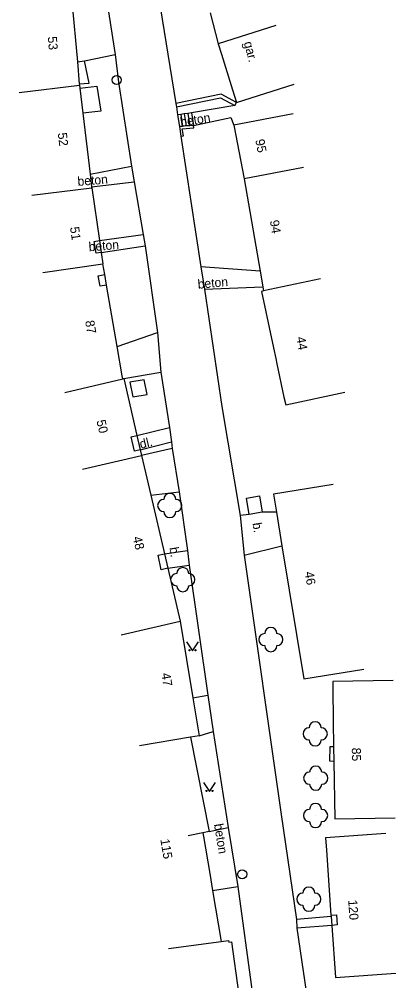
# Model space of a CAD drawing. Extents: x -582162 to -561283, y -1187583 to -1183539.
# Drawn here: x -571098.1 to -571067, y -1184224.9 to -1184145.5 of the extents above; entities that cross this region are included whole.
import ezdxf

# ---------------------------------------------------------------- set-up
doc = ezdxf.new("R2010")
doc.units = 0
for name, color, linetype in [('Vrstva 1', 7, 'Continuous'), ('Vrstva 10', 7, 'Continuous'), ('Vrstva 11', 7, 'Continuous'), ('Vrstva 14', 7, 'Continuous'), ('Vrstva 3', 7, 'Continuous'), ('Vrstva 4', 7, 'Continuous'), ('Vrstva 6', 7, 'Continuous'), ('Vrstva 9', 7, 'Continuous')]:
    doc.layers.add(name, color=color, linetype=linetype)

# ---------------------------------------------------------------- blocks, each defined once
blk = doc.blocks.new('1.079')
at = {"layer": 'Vrstva 1'}
for radius in [0.75, 0.001]:
    blk.add_circle((0, -0.001), radius, dxfattribs=at)
blk = doc.blocks.new('3.130')
at = {"layer": 'Vrstva 1'}
blk.add_circle((0, 0), 0.001, dxfattribs=at)
for centre, start, end in [((0, 1), 0, 180), ((-1, 0), 90, 270), ((1, 0), 270, 90), ((0, -1), 180, 360)]:
    blk.add_arc(centre, 1, start, end, dxfattribs=at)
blk = doc.blocks.new('3.140')
at = {"layer": 'Vrstva 1'}
blk.add_lwpolyline([(-1, 1.5), (0, 0), (1, 1.5)], dxfattribs=at)
for centre in [(-0.5, 0.1), (0.5, 0.1)]:
    blk.add_circle(centre, 0.1, dxfattribs=at)

msp = doc.modelspace()

# ---------------------------------------------------------------- linework, layer by layer
at = {"layer": 'Vrstva 10'}
for points in [[(-571085.92, -1184109.89), (-571087.29, -1184117.32), (-571087.67, -1184120.44), (-571088.1, -1184127), (-571087.65, -1184135.85), (-571086.64, -1184143.41), (-571085.18, -1184152.42)], [(-571091.85, -1184136.74), (-571091.16, -1184141.83), (-571090.97, -1184143.44), (-571090.19, -1184148.39)], [(-571092.73, -1184148.91), (-571090.19, -1184148.39)], [(-571090.19, -1184148.39), (-571089.9, -1184150.67), (-571088.84, -1184157.61)], [(-571093.31, -1184149), (-571092.73, -1184148.91)], [(-571093.15, -1184150.82), (-571092.34, -1184150.76), (-571092.73, -1184148.91)], [(-571093.11, -1184151.16), (-571091.71, -1184150.99), (-571091.38, -1184153.06), (-571092.86, -1184153.24)], [(-571085.18, -1184152.42), (-571085.13, -1184152.72)], [(-571085.13, -1184152.72), (-571085.04, -1184153.36)], [(-571084.78, -1184153.33), (-571085.04, -1184153.36)], [(-571085.04, -1184153.36), (-571084.89, -1184154.34)], [(-571084.48, -1184153.29), (-571084.78, -1184153.33)], [(-571084.78, -1184153.33), (-571084.62, -1184154.32)], [(-571084.18, -1184153.25), (-571084.48, -1184153.29)], [(-571084.48, -1184153.29), (-571084.32, -1184154.29)], [(-571083.89, -1184153.21), (-571084.18, -1184153.25)], [(-571084.18, -1184153.25), (-571084.02, -1184154.27)], [(-571080.31, -1184152.61), (-571083.89, -1184153.21)], [(-571083.89, -1184153.21), (-571083.72, -1184154.24)], [(-571083.72, -1184154.24), (-571080.63, -1184153.58), (-571080.39, -1184154.21)], [(-571084.89, -1184154.34), (-571084.77, -1184155.14)], [(-571084.77, -1184155.14), (-571083.11, -1184165.93)], [(-571092.26, -1184158.28), (-571088.84, -1184157.61)], [(-571088.84, -1184157.61), (-571088.62, -1184158.91)], [(-571092.13, -1184159.31), (-571088.62, -1184158.91)], [(-571088.62, -1184158.91), (-571087.88, -1184163.24)], [(-571091.48, -1184163.75), (-571087.88, -1184163.24)], [(-571087.88, -1184163.24), (-571087.71, -1184164.18)], [(-571091.34, -1184164.74), (-571087.71, -1184164.18)], [(-571087.71, -1184164.18), (-571086.7, -1184171.33)], [(-571083.11, -1184165.93), (-571082.81, -1184167.77)], [(-571078.22, -1184166.28), (-571083.11, -1184165.93)], [(-571082.81, -1184167.77), (-571078, -1184167.57)], [(-571082.81, -1184167.77), (-571081.37, -1184177.45), (-571079.86, -1184186.45)], [(-571090.02, -1184172.5), (-571086.7, -1184171.33)], [(-571086.7, -1184171.33), (-571086.42, -1184174.63)], [(-571089.48, -1184175.15), (-571086.42, -1184174.63)], [(-571086.42, -1184174.63), (-571085.71, -1184179.19)], [(-571087.8, -1184175.24), (-571088.99, -1184175.44), (-571088.74, -1184176.65), (-571087.55, -1184176.45), (-571087.8, -1184175.24)], [(-571088.39, -1184179.85), (-571085.71, -1184179.19)], [(-571085.71, -1184179.19), (-571085.53, -1184180.38)], [(-571088.12, -1184181.02), (-571085.53, -1184180.38)], [(-571085.53, -1184180.38), (-571085.48, -1184180.91)], [(-571085.48, -1184180.91), (-571088.01, -1184181.49)], [(-571085.48, -1184180.91), (-571084.9, -1184184.49)], [(-571087.25, -1184184.78), (-571084.9, -1184184.49)], [(-571084.9, -1184184.49), (-571084.23, -1184189.35)], [(-571079.12, -1184186.36), (-571079.35, -1184185.03), (-571078.28, -1184184.84), (-571078.05, -1184186.17)], [(-571079.12, -1184186.36), (-571079.86, -1184186.45)], [(-571079.86, -1184186.45), (-571079.54, -1184189.74)], [(-571078.05, -1184186.17), (-571079.12, -1184186.36)], [(-571076.88, -1184186.18), (-571078.05, -1184186.17)], [(-571079.54, -1184189.74), (-571076.42, -1184188.96)], [(-571086.12, -1184189.61), (-571084.23, -1184189.35)], [(-571084.23, -1184189.35), (-571084.07, -1184190.55)], [(-571079.54, -1184189.74), (-571076.47, -1184211.13), (-571075.22, -1184219.81)], [(-571085.84, -1184190.8), (-571084.07, -1184190.55)], [(-571084.07, -1184190.55), (-571082.54, -1184201.3)], [(-571083.77, -1184201.51), (-571082.54, -1184201.3)], [(-571082.54, -1184201.3), (-571082.09, -1184204.3)], [(-571083.25, -1184204.64), (-571082.09, -1184204.3)], [(-571082.09, -1184204.3), (-571080.87, -1184212.21)], [(-571072.13, -1184206.76), (-571072.47, -1184206.75), (-571072.44, -1184205.52), (-571072.15, -1184205.53)], [(-571082.42, -1184212.55), (-571080.87, -1184212.21)], [(-571080.87, -1184212.21), (-571080.05, -1184217.08)], [(-571082.14, -1184217.43), (-571080.05, -1184217.08)], [(-571080.05, -1184217.08), (-571078.89, -1184225.77)], [(-571072.36, -1184219.57), (-571075.22, -1184219.81)], [(-571075.22, -1184219.81), (-571075.19, -1184220.54)], [(-571072.31, -1184220.3), (-571075.19, -1184220.54)], [(-571075.19, -1184220.54), (-571072.2, -1184240.9), (-571070.07, -1184255.5)]]:
    msp.add_lwpolyline(points, dxfattribs=at)
at = {"layer": 'Vrstva 4'}
for points in [[(-571093.77, -1184143.97), (-571093.31, -1184149)], [(-571082.35, -1184144.95), (-571081.69, -1184147.51)], [(-571076.93, -1184146), (-571081.69, -1184147.51)], [(-571081.69, -1184147.51), (-571081.42, -1184148.37)], [(-571093.31, -1184149), (-571093.15, -1184150.82)], [(-571098.11, -1184151.52), (-571093.14, -1184150.92)], [(-571093.15, -1184150.82), (-571093.14, -1184150.92)], [(-571093.14, -1184150.92), (-571093.11, -1184151.16)], [(-571080.16, -1184152.34), (-571075.4, -1184150.84)], [(-571093.11, -1184151.16), (-571092.86, -1184153.24)], [(-571080.49, -1184151.3), (-571080.16, -1184152.34)], [(-571092.86, -1184153.24), (-571092.26, -1184158.28)], [(-571075.48, -1184153.28), (-571080.39, -1184154.21)], [(-571080.39, -1184154.21), (-571079.54, -1184158.65)], [(-571074.63, -1184157.71), (-571079.54, -1184158.65)], [(-571079.54, -1184158.65), (-571078.22, -1184166.28)], [(-571097.08, -1184160.01), (-571092.12, -1184159.41)], [(-571092.13, -1184159.31), (-571092.12, -1184159.41)], [(-571092.12, -1184159.41), (-571091.48, -1184163.75)], [(-571091.48, -1184163.75), (-571091.34, -1184164.74)], [(-571091.34, -1184164.74), (-571091.2, -1184165.68)], [(-571096.15, -1184166.4), (-571091.2, -1184165.68)], [(-571091.05, -1184166.55), (-571091.2, -1184165.68)], [(-571090.9, -1184167.42), (-571091.05, -1184166.55)], [(-571090.02, -1184172.5), (-571090.9, -1184167.42)], [(-571078, -1184167.57), (-571077.94, -1184167.91)], [(-571073.23, -1184166.9), (-571077.94, -1184167.91)], [(-571077.94, -1184167.91), (-571078.12, -1184167.95), (-571077.12, -1184172.6)], [(-571076.93, -1184173.5), (-571076.84, -1184173.92)], [(-571094.35, -1184176.29), (-571089.56, -1184175.17)], [(-571089.56, -1184175.17), (-571089.61, -1184174.91)], [(-571089.56, -1184175.17), (-571089.48, -1184175.15)], [(-571089.48, -1184175.15), (-571088.39, -1184179.85)], [(-571076.25, -1184176.67), (-571076.11, -1184177.32), (-571071.22, -1184176.27)], [(-571088.39, -1184179.85), (-571088.12, -1184181.02)], [(-571088.12, -1184181.02), (-571088.01, -1184181.49)], [(-571092.88, -1184182.62), (-571088.01, -1184181.49)], [(-571088.01, -1184181.49), (-571087.9, -1184181.96)], [(-571072.19, -1184183.88), (-571077.12, -1184184.7), (-571076.88, -1184186.18)], [(-571087.25, -1184184.78), (-571086.12, -1184189.61)], [(-571076.42, -1184188.96), (-571074.61, -1184199.95), (-571069.67, -1184199.14)], [(-571086.12, -1184189.61), (-571085.84, -1184190.8)], [(-571085.84, -1184190.8), (-571084.82, -1184195.18)], [(-571089.69, -1184196.31), (-571084.82, -1184195.18)], [(-571084.82, -1184195.18), (-571083.77, -1184201.51)], [(-571067.23, -1184200.09), (-571072.23, -1184200.17), (-571072.22, -1184200.7)], [(-571083.77, -1184201.51), (-571083.25, -1184204.64)], [(-571072.18, -1184203.44), (-571072.15, -1184205.53)], [(-571083.97, -1184204.76), (-571088.18, -1184205.46)], [(-571083.25, -1184204.64), (-571083.97, -1184204.76)], [(-571083.97, -1184204.76), (-571082.42, -1184212.55)], [(-571072.15, -1184205.53), (-571072.15, -1184205.72)], [(-571072.13, -1184206.61), (-571072.13, -1184206.76)], [(-571072.13, -1184206.76), (-571072.06, -1184211.49), (-571067.06, -1184211.41)], [(-571082.94, -1184212.65), (-571084.16, -1184212.89)], [(-571082.42, -1184212.55), (-571082.94, -1184212.65)], [(-571082.94, -1184212.65), (-571082.89, -1184212.96)], [(-571067.83, -1184212.71), (-571072.81, -1184213.06), (-571072.74, -1184214.09)], [(-571082.38, -1184216.01), (-571082.14, -1184217.43)], [(-571082.14, -1184217.43), (-571081.44, -1184221.62)], [(-571072.54, -1184216.98), (-571072.37, -1184219.45)], [(-571072.37, -1184219.45), (-571072.36, -1184219.57)], [(-571072.36, -1184219.57), (-571072.31, -1184220.3)], [(-571072.31, -1184220.3), (-571072.01, -1184224.6), (-571067.02, -1184224.25)], [(-571085.78, -1184222.21), (-571081.44, -1184221.62)], [(-571081.44, -1184221.62), (-571080.82, -1184221.54), (-571080.8, -1184221.69), (-571080.59, -1184221.66), (-571080, -1184225.85)]]:
    msp.add_lwpolyline(points, dxfattribs=at)
at = {"layer": 'Vrstva 9'}
for points in [[(-571081.42, -1184148.37), (-571080.49, -1184151.3)], [(-571080.16, -1184152.34), (-571081.45, -1184151.66), (-571085.18, -1184152.42)], [(-571085.13, -1184152.72), (-571081.49, -1184151.97), (-571080.31, -1184152.61)], [(-571080.31, -1184152.61), (-571080.16, -1184152.34)], [(-571084.62, -1184154.32), (-571084.89, -1184154.34)], [(-571084.77, -1184155.14), (-571084.56, -1184155.11), (-571084.65, -1184154.52), (-571083.7, -1184154.43), (-571083.72, -1184154.24)], [(-571084.32, -1184154.29), (-571084.62, -1184154.32)], [(-571084.02, -1184154.27), (-571084.32, -1184154.29)], [(-571083.72, -1184154.24), (-571084.02, -1184154.27)], [(-571092.26, -1184158.28), (-571092.13, -1184159.31)], [(-571091.34, -1184164.74), (-571091.77, -1184164.8), (-571091.91, -1184163.82), (-571091.48, -1184163.75)], [(-571090.9, -1184167.42), (-571091.44, -1184167.51), (-571091.59, -1184166.65), (-571091.05, -1184166.55)], [(-571078.22, -1184166.28), (-571078, -1184167.57)], [(-571089.61, -1184174.91), (-571090.02, -1184172.5)], [(-571077.12, -1184172.6), (-571076.93, -1184173.5)], [(-571076.84, -1184173.92), (-571076.25, -1184176.67)], [(-571088.12, -1184181.02), (-571088.6, -1184181.13), (-571088.88, -1184179.96), (-571088.39, -1184179.85)], [(-571087.9, -1184181.96), (-571087.25, -1184184.78)], [(-571076.88, -1184186.18), (-571076.42, -1184188.96)], [(-571085.84, -1184190.8), (-571086.38, -1184190.93), (-571086.65, -1184189.74), (-571086.12, -1184189.61)], [(-571072.22, -1184200.7), (-571072.18, -1184203.44)], [(-571072.15, -1184205.72), (-571072.13, -1184206.61)], [(-571082.89, -1184212.96), (-571082.38, -1184216.01)], [(-571072.74, -1184214.09), (-571072.54, -1184216.98)], [(-571072.37, -1184219.45), (-571071.92, -1184219.42), (-571071.86, -1184220.26), (-571072.31, -1184220.3)]]:
    msp.add_lwpolyline(points, dxfattribs=at)

# ---------------------------------------------------------------- block references
at = {"layer": 'Vrstva 1', "xscale": 0.5, "yscale": 0.5}
for p in [(-571090.07, -1184150.49), (-571079.7, -1184216.08)]:
    msp.add_blockref('1.079', p, dxfattribs=at)
at = {"layer": 'Vrstva 11', "xscale": 0.5, "yscale": 0.5}
for p in [(-571085.68, -1184185.63), (-571084.61, -1184191.75), (-571077.34, -1184196.7), (-571073.67, -1184204.48), (-571073.63, -1184208.14), (-571073.64, -1184211.22), (-571074.2, -1184218.13)]:
    msp.add_blockref('3.130', p, dxfattribs=at)
at = {"layer": 'Vrstva 3', "xscale": 0.5, "yscale": 0.5}
for p in [(-571083.8, -1184197.63), (-571082.4, -1184209.25)]:
    msp.add_blockref('3.140', p, dxfattribs=at)

# ---------------------------------------------------------------- texts
at = {"layer": 'Vrstva 14'}
for s, rotation, p in [(' gar. ', 284.437, (-571079.64, -1184147.14)), (' beton', 9.478, (-571085.03, -1184154.4)), (' beton', 4.383, (-571093.55, -1184159.26)), (' beton', 4.383, (-571092.63, -1184164.66)), (' beton', 5.288, (-571083.62, -1184167.76)), (' dl.', 13.846, (-571088.34, -1184181.01)), (' b.', 279.356, (-571078.9, -1184186.82)), (' b.', 279.356, (-571085.76, -1184188.84)), (' beton', 279.504, (-571082.08, -1184211.68))]:
    msp.add_text(s, height=0.75, rotation=rotation, dxfattribs=at).set_placement(p)
at = {"layer": 'Vrstva 6'}
for s, rotation, p in [('53', 275.116, (-571095.76, -1184146.93)), ('52', 276.884, (-571094.93, -1184154.88)), ('95', 280.809, (-571078.62, -1184155.45)), ('94', 279.788, (-571077.42, -1184162.12)), ('51', 278.301, (-571093.92, -1184162.66)), ('87', 279.839, (-571092.67, -1184170.4)), ('44', 279.79, (-571075.23, -1184171.75)), ('50', 283.1, (-571091.74, -1184178.64)), ('48', 283.102, (-571088.74, -1184188.26)), ('46', 279.356, (-571074.54, -1184191.14)), ('47', 279.454, (-571086.38, -1184199.51)), ('85', 270.85, (-571070.65, -1184205.63)), ('115', 279.504, (-571086.46, -1184213.21)), ('120', 273.989, (-571070.95, -1184218.21))]:
    msp.add_text(s, height=0.75, rotation=rotation, dxfattribs=at).set_placement(p)

doc.saveas('drawing.dxf')
